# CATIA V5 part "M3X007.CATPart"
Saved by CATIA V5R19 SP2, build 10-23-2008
Part number: M3X007
Definition: design
Nomenclature: M3X007
Source: Unknown
Bounding box of the stored display mesh (mm): x -3.002 to 3.002, y -3.002 to 3.002, z 0 to 6
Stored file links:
  Z:\fausse table rondelle-20220905T211342Z-001\fausse table rondelle\M3X007.CATPart
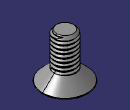
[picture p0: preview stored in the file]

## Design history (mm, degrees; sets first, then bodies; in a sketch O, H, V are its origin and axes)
AxisSystem1: origin (0, 0, 0), X (1, 0, 0), Y (0, 1, 0), Z (0, 0, 1)
Set1
  DatumSurface1 "OPEN_SHELL #267437"
Body1 (main body)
